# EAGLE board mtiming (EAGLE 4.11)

No outline drawn. Coordinates in mm, seen from the top.
Copper layers (1*16): Top 0.035mm / dielectric 1.5mm / Bottom 0.035mm
Design rules "default": minimum track width 10mil, minimum drill 24mil, track to track 8mil, track to pad 8mil, pad to pad 8mil, via to via 8mil, smd to smd 8mil, copper to edge 25mil, drill to drill 8mil, minimum pad ring 10mil, minimum via ring 8mil, stop-mask expansion 4mil, vias tented up to drill 0mil, thermal gap 10mil
Net classes: 1 Supply: width 0.635 mm

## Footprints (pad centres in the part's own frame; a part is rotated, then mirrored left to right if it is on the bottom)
CBLOCK = hole 6.452: 7.938,68.263; 42.862,68.263

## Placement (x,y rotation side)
U$1  [CBLOCK]  0,136.53 0 top
U$2  [CBLOCK]  50.8,136.53 0 top
U$3  [CBLOCK]  0,273.05 0 top
U$4  [CBLOCK]  50.8,273.05 0 top
U$5  [CBLOCK]  101.6,273.05 0 top
U$6  [CBLOCK]  101.6,136.53 0 top
U$7  [CBLOCK]  457.2,273.05 0 top
U$8  [CBLOCK]  457.2,136.53 0 top
U$9  [CBLOCK]  457.2,0 0 top
U$10  [CBLOCK]  406.4,273.05 0 top
U$11  [CBLOCK]  406.4,136.53 0 top
U$12  [CBLOCK]  406.4,0 0 top
U$13  [CBLOCK]  355.6,273.05 0 top
U$14  [CBLOCK]  355.6,136.53 0 top
U$15  [CBLOCK]  355.6,0 0 top
U$16  [CBLOCK]  152.4,273.05 0 top
U$17  [CBLOCK]  152.4,136.53 0 top
U$18  [CBLOCK]  0,0 0 top
U$19  [CBLOCK]  50.8,0 0 top
U$20  [CBLOCK]  152.4,0 0 top
U$21  [CBLOCK]  101.6,0 0 top
U$22  [CBLOCK]  203.2,273.05 0 top
U$23  [CBLOCK]  203.2,136.53 0 top
U$24  [CBLOCK]  203.2,0 0 top
U$25  [CBLOCK]  254,136.53 0 top
U$26  [CBLOCK]  304.8,136.53 0 top
U$27  [CBLOCK]  254,273.05 0 top
U$28  [CBLOCK]  304.8,273.05 0 top
U$29  [CBLOCK]  304.8,0 0 top
U$30  [CBLOCK]  254,0 0 top

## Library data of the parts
U$1-U$30 = dec-r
